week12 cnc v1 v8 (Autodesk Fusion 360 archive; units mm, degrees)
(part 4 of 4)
sketch "Sketch2" plane through (0, 0, 0) normal (-1, 0, 0) x axis (0, -1, 0)
  line L1 (-685.4, 300) -> (-685.4, 288)
  line L2 (-716, 300) -> (-685.4, 300)
  line L3 (-716, 12) -> (-716, 300)
  line L4 (-525.1111, 12) -> (-716, 12)
  line L5 (-525.1111, 0) -> (-525.1111, 12)
  line L6 (-432.8889, 0) -> (-525.1111, 0)
  line L7 (-432.8889, 12) -> (-432.8889, 0)
  line L8 (-243.1111, 12) -> (-432.8889, 12)
  line L9 (-243.1111, 0) -> (-243.1111, 12)
  line L10 (-150.8889, 0) -> (-243.1111, 0)
  line L11 (-150.8889, 12) -> (-150.8889, 0)
  line L12 (0, 12) -> (-150.8889, 12)
  line L13 (0, 300) -> (0, 12)
  line L14 (-656.6, 300) -> (0, 300)
  line L15 (-656.6, 288) -> (-656.6, 300)
  line L16 (-685.4, 288) -> (-656.6, 288)
  line L17 (-614, 12) -> (-626, 12)
  line L18 (-614, 300) -> (-614, 12)
  line L19 (-626, 300) -> (-614, 300)
  line L20 (-626, 12) -> (-626, 300)
  line L21 (-332, 12) -> (-344, 12)
  line L22 (-332, 300) -> (-332, 12)
  line L23 (-344, 300) -> (-332, 300)
  line L24 (-344, 12) -> (-344, 300)
  line L25 (-50, 12) -> (-62, 12)
  line L26 (-50, 300) -> (-50, 12)
  line L27 (-62, 300) -> (-50, 300)
  line L28 (-62, 12) -> (-62, 300)
  line L29 (-896, 12) -> (-908, 12)
  line L30 (-896, 300) -> (-896, 12)
  line L31 (-908, 300) -> (-896, 300)
  line L32 (-908, 12) -> (-908, 300)
  line L33 (-50, 156) -> (-908, 156)
  line L34 (-896, 106) -> (-908, 106)
  line L35 (-614, 106) -> (-626, 106)
  line L36 (-332, 106) -> (-344, 106)
  line L37 (-50, 106) -> (-62, 106)
  line L38 (-50, 206) -> (-62, 206)
  line L39 (-332, 206) -> (-344, 206)
  line L40 (-896, 206) -> (-908, 206)
  line L41 (-614, 206) -> (-626, 206)
  line L42 (-635, 30.4) -> (-707, 30.4)
  line L43 (-635, 48.8) -> (-635, 30.4)
  line L44 (-707, 48.8) -> (-635, 48.8)
  line L45 (-707, 30.4) -> (-707, 48.8)
  line L46 (-707, 300) -> (-635, 300)
  line L47 (-707, 288) -> (-707, 300)
  line L48 (-635, 288) -> (-707, 288)
  line L49 (-635, 300) -> (-635, 288)
  line L50 (-635, 85.6) -> (-635, 67.2)
  line L51 (-707, 67.2) -> (-707, 85.6)
  line L52 (-635, 67.2) -> (-707, 67.2)
  line L53 (-707, 85.6) -> (-635, 85.6)
  line L54 (-635, 122.4) -> (-635, 104)
  line L55 (-707, 159.2) -> (-635, 159.2)
  line L56 (-707, 104) -> (-707, 122.4)
  line L57 (-707, 140.8) -> (-707, 159.2)
  line L58 (-635, 140.8) -> (-707, 140.8)
  line L59 (-635, 159.2) -> (-635, 140.8)
  line L60 (-707, 122.4) -> (-635, 122.4)
  line L61 (-635, 104) -> (-707, 104)
  line L62 (-707, 232.8) -> (-635, 232.8)
  line L63 (-635, 232.8) -> (-635, 214.4)
  line L64 (-635, 177.6) -> (-707, 177.6)
  line L65 (-707, 269.6) -> (-635, 269.6)
  line L66 (-635, 251.2) -> (-707, 251.2)
  line L67 (-707, 214.4) -> (-707, 232.8)
  line L68 (-707, 177.6) -> (-707, 196)
  line L69 (-707, 196) -> (-635, 196)
  line L70 (-635, 214.4) -> (-707, 214.4)
  line L71 (-635, 269.6) -> (-635, 251.2)
  line L72 (-707, 251.2) -> (-707, 269.6)
  line L73 (-635, 196) -> (-635, 177.6)
  line L74 (-671, 12) -> (-671, 30.4)
  line L75 (-671, 67.2) -> (-671, 48.8)
  line L76 (-671, 104) -> (-671, 85.6)
  line L77 (-671, 140.8) -> (-671, 122.4)
  line L78 (-671, 177.6) -> (-671, 159.2)
  line L79 (-671, 214.4) -> (-671, 196)
  line L80 (-671, 251.2) -> (-671, 232.8)
  line L81 (-671, 288) -> (-671, 269.6)
  line L82 (-716, 288) -> (-707, 288)
  line L83 (-626, 288) -> (-635, 288)
  line L84 (-525.1111, 0) -> (-716, 0)
  line L85 (-525.1111, 12) -> (-525.1111, 0)
  line L86 (-716, 12) -> (-525.1111, 12)
  line L87 (-716, 0) -> (-716, 12)
  line L88 (-614, 0) -> (-614, 12)
  line L89 (-116, 228) -> (-116, 84)
  line L90 (-206, 228) -> (-116, 228)
  line L91 (-116, 84) -> (-206, 84)
  line L92 (-488, 228) -> (-398, 228)
  line L93 (-398, 84) -> (-488, 84)
  line L94 (-398, 228) -> (-398, 84)
  line L95 (-680, 228) -> (-680, 84)
  line L96 (-770, 228) -> (-680, 228)
  line L97 (-680, 84) -> (-770, 84)
  arc A1 centre (-206, 156) radius 72 clockwise from (-206, 84) to (-206, 228)
  arc A2 centre (-488, 156) radius 72 clockwise from (-488, 84) to (-488, 228)
  arc A3 centre (-770, 156) radius 72 clockwise from (-770, 84) to (-770, 228)
  point P34 (-908, 156)
  point P35 (-50, 156)
  point P36 (-908, 106)
  point P37 (-896, 106)
  point P38 (-626, 106)
  point P39 (-614, 106)
  point P40 (-344, 106)
  point P41 (-332, 106)
  point P42 (-62, 106)
  point P43 (-50, 106)
  point P46 (-908, 206)
  point P48 (-896, 206)
  point P50 (-626, 206)
  point P47 (-614, 206)
  point P51 (-344, 206)
  point P44 (-332, 206)
  point P49 (-62, 206)
  point P45 (-50, 206)
  point P84 (-671, 30.4)
  point P85 (-671, 12)
  point P86 (-671, 48.8)
  point P87 (-671, 67.2)
  point P88 (-671, 85.6)
  point P89 (-671, 104)
  point P90 (-671, 122.4)
  point P91 (-671, 140.8)
  point P92 (-671, 159.2)
  point P93 (-671, 177.6)
  point P94 (-671, 196)
  point P95 (-671, 214.4)
  point P96 (-671, 232.8)
  point P97 (-671, 251.2)
  point P98 (-671, 269.6)
  point P99 (-671, 288)
  point P58 (-707, 288)
  point P100 (-707, 288)
  point P101 (-716, 288)
  point P59 (-635, 288)
  point P102 (-635, 288)
  point P103 (-626, 288)
  point P19 (-614, 12)
  point P108 (-614, 12)
  point P109 (-614, 0)
  point P115 (-278, 156)
  point P117 (-560, 156)
  point P126 (-842, 156)
  point P110 (-116, 84)
  point P111 (-116, 228)
  point P118 (-398, 228)
  point P120 (-398, 84)
  point P123 (-680, 228)
  point P127 (-680, 84)
  midpoint L32 P34
  midpoint L26 P35
  coincident L32 P36
  coincident L30 P37
  perpendicular L30 L34
  coincident L20 P38
  coincident L18 P39
  perpendicular L18 L35
  coincident L24 P40
  coincident L22 P41
  perpendicular L22 L36
  coincident L28 P42
  coincident L26 P43
  perpendicular L26 L37
  collinear L34 L35
  collinear L35 L36
  collinear L36 L37
  symmetric L33 P36 P46
  symmetric L33 P37 P48
  symmetric L33 P38 P50
  symmetric L33 P39 P47
  symmetric L33 P40 P51
  symmetric L33 P41 P44
  symmetric L33 P42 P49
  symmetric L33 P43 P45
  horizontal L42
  vertical L43
  horizontal L44
  vertical L45
  collinear L45 L47
  collinear L43 L49
  horizontal L52
  vertical L50
  horizontal L53
  vertical L51
  horizontal L61
  vertical L54
  horizontal L60
  vertical L56
  horizontal L58
  vertical L59
  horizontal L55
  vertical L57
  horizontal L64
  vertical L73
  horizontal L69
  vertical L68
  horizontal L70
  vertical L63
  horizontal L62
  vertical L67
  horizontal L66
  vertical L71
  horizontal L65
  vertical L72
  equal L45 L51
  equal L51 L56
  equal L56 L57
  equal L57 L68
  equal L67 L68
  equal L67 L72
  collinear L57 L72
  collinear L51 L57
  collinear L51 L67
  collinear L45 L67
  collinear L45 L68
  collinear L56 L68
  collinear L43 L54
  collinear L54 L59
  collinear L59 L63
  collinear L63 L73
  collinear L50 L73
  collinear L50 L71
  midpoint L42 P84
  coincident L4 P85
  perpendicular L4 L74
  midpoint L44 P86
  midpoint L52 P87
  midpoint L53 P88
  midpoint L61 P89
  midpoint L60 P90
  midpoint L58 P91
  midpoint L55 P92
  midpoint L64 P93
  midpoint L69 P94
  midpoint L70 P95
  midpoint L62 P96
  midpoint L66 P97
  midpoint L65 P98
  midpoint L48 P99
  equal L45 L74
  equal L79 L80
  equal L77 L80
  equal L75 L77
  equal L74 L75
  equal L74 L76
  equal L76 L78
  equal L78 L81
  coincident P58 P100
  coincident L3 P101
  perpendicular L3 L82
  coincident P59 P102
  coincident L20 P103
  perpendicular L20 L83
  coincident P19 P108
  coincident L84 P109
  perpendicular L84 L88
  vertical L89
  perpendicular L89 L90
  tangent L90 A1
  symmetric L33 L90 L91
  tangent A1 L91
  midpoint A1 P115
  vertical L94
  perpendicular L92 L94
  tangent A2 L92
  tangent A2 L93
  midpoint P117 A2
  perpendicular L93 L94
  vertical L95
  perpendicular L95 L96
  tangent L96 A3
  tangent L97 A3
  midpoint P126 A3
  perpendicular L95 L97
  coincident L33 P117
  coincident L33 P126
  equal L92 L96
  dimension "d55" distance L34 L40 = 100 (= "width / 3")
  dimension "d58" distance L22 L28 = 270
  dimension "d59" distance L28 L89 = 54 (= "d58 / 5")
  dimension "d60" distance L12 L14 = 288
  dimension "d61" distance L22 P115 = 54 (= "d58 / 5")
  dimension "d62" distance P110 P111 = 144 (= "d60 * 0.5")
  dimension "d63" distance P118 P120 = 144 (= "d60 * 0.5")
  dimension "d64" distance P123 P127 = 144 (= "d60 * 0.5")
  dimension "d66" distance L24 L94 = 54 (= "d59")
  dimension "d67" distance L30 P126 = 54 (= "d65")
extrude "Extrude10" cut sketch "Sketch2" profile of L42 L43 L44 L45 L50 L51 L52 L53 L54 L55 L56 L57 L58 L59 L60 L61 L62 L63 L64 L65 L66 L67 L68 L69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 to an object
extrude "Extrude5" cut sketch "Sketch2" profile of L89 L90 A1 L91 A2 L92 L93 L94 to an object
extrude "Extrude6" sketch "Sketch2" profile of L3 L51 L53 L55 L56 L57 L58 L60 L61 L64 L67 L68 L69 L70 L89 L90 A1 L91 A2 L92 L93 L94 L95 L96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 to an object
sketch "Sketch3" plane through (541.3333, 0, 0) normal (1, 0, 0) x axis (0, 1, 0)
  line L1 (626, 12) -> (332, 12)
  line L2 (626, 300) -> (626, 12)
  line L3 (332, 300) -> (626, 300)
  line L4 (332, 12) -> (332, 300)
  line L5 (626, 12) -> (614, 12)
  line L6 (626, 300) -> (626, 12)
  line L7 (614, 300) -> (626, 300)
  line L8 (614, 12) -> (614, 300)
  line L9 (344, 12) -> (332, 12)
  line L10 (344, 300) -> (344, 12)
  line L11 (332, 300) -> (344, 300)
  line L12 (332, 12) -> (332, 300)
  line L13 (62, 12) -> (50, 12)
  line L14 (62, 300) -> (62, 12)
  line L15 (50, 300) -> (62, 300)
  line L16 (50, 12) -> (50, 300)
  line L17 (116, 84) -> (206, 84)
  line L18 (206, 228) -> (116, 228)
  line L19 (116, 228) -> (116, 84)
  line L20 (62, 228) -> (165.5, 228)
  line L21 (62, 84) -> (165.5, 84)
  line L22 (344, 228) -> (447.5, 228)
  line L23 (344, 84) -> (447.5, 84)
  line L24 (626, 228) -> (729.5, 228)
  line L25 (626, 84) -> (729.5, 84)
  line L26 (908, 12) -> (896, 12)
  line L27 (908, 300) -> (908, 12)
  line L28 (896, 300) -> (908, 300)
  line L29 (896, 12) -> (896, 300)
  line L30 (50, 156) -> (908, 156)
  line L31 (896, 106) -> (908, 106)
  line L32 (614, 106) -> (626, 106)
  line L33 (332, 106) -> (344, 106)
  line L34 (50, 106) -> (62, 106)
  line L35 (896, 206) -> (908, 206)
  line L36 (614, 206) -> (626, 206)
  line L37 (332, 206) -> (344, 206)
  line L38 (50, 206) -> (62, 206)
  line L39 (626, 300) -> (626, 228)
  line L40 (614, 264) -> (626, 264)
  line L41 (614, 252) -> (626, 252)
  line L42 (614, 276) -> (626, 276)
  line L43 (614, 60) -> (626, 60)
  line L44 (614, 36) -> (626, 36)
  line L45 (479, 300) -> (479, 12)
  line L46 (197, 300) -> (197, 12)
  line L47 (344, 36) -> (332, 36)
  line L48 (344, 60) -> (332, 60)
  line L49 (344, 252) -> (332, 252)
  line L50 (344, 276) -> (332, 276)
  line L51 (50, 36) -> (62, 36)
  line L52 (50, 60) -> (62, 60)
  line L53 (50, 252) -> (62, 252)
  line L54 (50, 276) -> (62, 276)
  arc A1 centre (206, 156) radius 72 clockwise from (206, 228) to (206, 84)
  arc A2 centre (165.5, 156) radius 72 clockwise from (165.5, 228) to (165.5, 84)
  arc A3 centre (447.5, 156) radius 72 clockwise from (447.5, 228) to (447.5, 84)
  arc A4 centre (729.5, 156) radius 72 clockwise from (729.5, 228) to (729.5, 84)
  point P23 (165.5, 228)
  point P24 (62, 228)
  point P25 (165.5, 84)
  point P26 (62, 84)
  point P28 (237.5, 156)
  point P33 (344, 228)
  point P30 (344, 84)
  point P38 (626, 228)
  point P35 (626, 84)
  point P43 (908, 156)
  point P44 (50, 156)
  point P45 (908, 106)
  point P46 (896, 106)
  point P47 (626, 106)
  point P48 (614, 106)
  point P49 (344, 106)
  point P50 (332, 106)
  point P51 (62, 106)
  point P52 (50, 106)
  point P53 (908, 206)
  point P54 (896, 206)
  point P55 (626, 206)
  point P56 (614, 206)
  point P57 (344, 206)
  point P58 (332, 206)
  point P59 (62, 206)
  point P60 (50, 206)
  point P4 (626, 300)
  point P61 (626, 300)
  point P62 (626, 264)
  point P63 (614, 264)
  point P64 (626, 252)
  point P65 (614, 252)
  point P66 (626, 276)
  point P67 (614, 276)
  point P68 (626, 60)
  point P69 (614, 60)
  point P70 (626, 36)
  point P71 (614, 36)
  point P74 (197, 12)
  point P72 (479, 12)
  point P80 (332, 252)
  point P81 (344, 252)
  point P82 (332, 276)
  point P83 (344, 276)
  point P78 (332, 60)
  point P79 (344, 60)
  point P76 (332, 36)
  point P77 (344, 36)
  point P84 (62, 36)
  point P85 (50, 36)
  point P86 (62, 60)
  point P87 (50, 60)
  point P88 (62, 252)
  point P89 (50, 252)
  point P90 (62, 276)
  point P91 (50, 276)
  point P92 (908, 300)
  point P93 (896, 300)
  point P94 (908, 300)
  point P95 (896, 300)
  point P96 (908, 300)
  point P97 (896, 300)
  coincident L18 P23
  coincident L14 P24
  perpendicular L14 L20
  coincident L17 P25
  coincident L14 P26
  perpendicular L14 L21
  tangent L20 A2
  tangent L21 A2
  midpoint A2 P28
  tangent L22 A3
  tangent A3 L23
  tangent L24 A4
  tangent A4 L25
  coincident L10 P33
  coincident L10 P30
  collinear L20 L22
  collinear L21 L23
  equal L21 L23
  coincident L6 P38
  coincident L6 P35
  collinear L22 L24
  collinear L23 L25
  equal L23 L25
  midpoint L27 P43
  midpoint L16 P44
  coincident L27 P45
  coincident L29 P46
  perpendicular L29 L31
  coincident L6 P47
  coincident L8 P48
  perpendicular L8 L32
  coincident L10 P49
  coincident L12 P50
  perpendicular L12 L33
  coincident L14 P51
  coincident L16 P52
  perpendicular L16 L34
  collinear L33 L34
  collinear L32 L33
  collinear L31 L32
  symmetric L30 P45 P53
  symmetric L30 P46 P54
  symmetric L30 P47 P55
  symmetric L30 P48 P56
  symmetric L30 P49 P57
  symmetric L30 P50 P58
  symmetric L30 P51 P59
  symmetric L30 P52 P60
  coincident P4 P61
  midpoint L39 P62
  coincident L8 P63
  perpendicular L8 L40
  coincident L39 P64
  coincident L8 P65
  perpendicular L8 L41
  coincident L6 P66
  coincident L8 P67
  perpendicular L8 L42
  symmetric L40 L41 L42
  symmetric L30 P64 P68
  symmetric L30 P65 P69
  symmetric L30 P66 P70
  symmetric L30 P67 P71
  perpendicular L30 L45
  perpendicular L30 L46
  symmetric L8 L10 L45
  equal L45 L46
  equal L10 L45
  coincident L1 P74
  coincident L1 P72
  symmetric P64 L45 P80
  symmetric P65 L45 P81
  symmetric P66 L45 P82
  symmetric P67 L45 P83
  symmetric P68 L45 P78
  symmetric P69 L45 P79
  symmetric P70 L45 P76
  symmetric P71 L45 P77
  symmetric L46 P76 P84
  symmetric L46 P77 P85
  symmetric L46 P78 P86
  symmetric L46 P79 P87
  symmetric L46 P80 P88
  symmetric L46 P81 P89
  symmetric L46 P82 P90
  symmetric L46 P83 P91
  dimension "d73" distance L12 L14 = 270
  dimension "d74" distance L12 P28 = 94.5 (= "d73 * 0.35")
  dimension "d75" distance L31 L35 = 100 (= "width / 3")
  dimension "d76" distance L3 L24 = 72
  dimension "d77" distance L41 L42 = 24 (= "d76 / 3")
  dimension "d87" distance P92 P93 = 12
  dimension "d88" distance P94 P95 = 12
  dimension "d89" distance P96 P97 = 12
extrude "Extrude7" cut sketch "Sketch3" profile of L1 L2 L3 L4 L5 L6 L7 L8 L9 L10 L11 L12 L22 A3 L23 L32 L33 L36 L37 L41 L42 L43 L44 L47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 to an object
extrude "Extrude8" sketch "Sketch3" profile of L1 L2 L3 L4 L5 L6 L7 L8 L9 L10 L11 L12 L13 L14 L15 L16 L20 L21 A2 L24 A4 L25 L26 L27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 to an object
extrude "Extrude9" cut sketch "Sketch2" profile of L18 L20 L22 L24 L26 L28 L30 L32 L34 L35 L36 L37 L38 L39 L40 L41 to an object
combine "Combine13"
combine "Combine14"
combine "Combine15" Linear Dimension-10 54 (= "d61") named "d65"
combine "Combine16"
sketch "Sketch5" plane through (0, 626, 0) normal (0, 1, 0) x axis (-1, 0, 0)
  line L1 (-12, 300) -> (-12, 206)
  line L2 (-104.2222, 300) -> (-12, 300)
  line L3 (-104.2222, 288) -> (-104.2222, 300)
  line L4 (-196.4444, 288) -> (-104.2222, 288)
  line L5 (-196.4444, 300) -> (-196.4444, 288)
  line L6 (-818, 300) -> (-196.4444, 300)
  line L7 (-818, 206) -> (-818, 300)
  line L8 (-830, 206) -> (-818, 206)
  line L9 (-830, 106) -> (-830, 206)
  line L10 (-818, 106) -> (-830, 106)
  line L11 (-818, 12) -> (-818, 106)
  line L12 (-725.7778, 12) -> (-818, 12)
  line L13 (-725.7778, 0) -> (-725.7778, 12)
  line L14 (-633.5556, 0) -> (-725.7778, 0)
  line L15 (-633.5556, 12) -> (-633.5556, 0)
  line L16 (-196.4444, 12) -> (-633.5556, 12)
  line L17 (-196.4444, 0) -> (-196.4444, 12)
  line L18 (-104.2222, 0) -> (-196.4444, 0)
  line L19 (-104.2222, 12) -> (-104.2222, 0)
  line L20 (-12, 12) -> (-104.2222, 12)
  line L21 (-12, 106) -> (-12, 12)
  line L22 (0, 106) -> (-12, 106)
  line L23 (0, 206) -> (0, 106)
  line L24 (-12, 206) -> (0, 206)
  line L25 (-300.6667, 36) -> (-288.6667, 36)
  line L26 (-300.6667, 60) -> (-300.6667, 36)
  line L27 (-288.6667, 60) -> (-300.6667, 60)
  line L28 (-288.6667, 36) -> (-288.6667, 60)
  line L29 (-300.6667, 276) -> (-300.6667, 252)
  line L30 (-288.6667, 276) -> (-300.6667, 276)
  line L31 (-288.6667, 252) -> (-288.6667, 276)
  line L32 (-300.6667, 252) -> (-288.6667, 252)
  line L33 (-541.3333, 106) -> (-529.3333, 106)
  line L34 (-541.3333, 206) -> (-541.3333, 106)
  line L35 (-529.3333, 206) -> (-541.3333, 206)
  line L36 (-529.3333, 106) -> (-529.3333, 206)
  line L37 (-750, 50) -> (-650, 50)
  line L38 (-750, 140) -> (-750, 50)
  line L39 (-650, 140) -> (-750, 140)
  line L40 (-650, 50) -> (-650, 140)
  point P38 (-650, 50)
  point P39 (-750, 50)
  point P41 (-650, 140)
  horizontal L37
  vertical L38
  horizontal L39
  vertical L40
  dimension "d123" distance P38 P39 = 100
  dimension "d124" distance P38 P41 = 90
extrude "Extrude11" cut sketch "Sketch5" profile of L37 L38 L39 L40 no distance stored
sketch "Sketch6" plane through (0, 344, 0) normal (0, 1, 0) x axis (-1, 0, 0)
  line L1 (-300.6667, 106) -> (-288.6667, 106)
  line L2 (-300.6667, 206) -> (-300.6667, 106)
  line L3 (-288.6667, 206) -> (-300.6667, 206)
  line L4 (-288.6667, 106) -> (-288.6667, 206)
  line L5 (-529.3333, 276) -> (-541.3333, 276)
  line L6 (-529.3333, 252) -> (-529.3333, 276)
  line L7 (-541.3333, 252) -> (-529.3333, 252)
  line L8 (-541.3333, 276) -> (-541.3333, 252)
  line L9 (-541.3333, 36) -> (-529.3333, 36)
  line L10 (-541.3333, 60) -> (-541.3333, 36)
  line L11 (-529.3333, 60) -> (-541.3333, 60)
  line L12 (-529.3333, 36) -> (-529.3333, 60)
  line L13 (-818, 206) -> (-818, 300)
  line L14 (-830, 206) -> (-818, 206)
  line L15 (-830, 106) -> (-830, 206)
  line L16 (-818, 106) -> (-830, 106)
  line L17 (-818, 12) -> (-818, 106)
  line L18 (-725.7778, 12) -> (-818, 12)
  line L19 (-725.7778, 0) -> (-725.7778, 12)
  line L20 (-633.5556, 0) -> (-725.7778, 0)
  line L21 (-633.5556, 12) -> (-633.5556, 0)
  line L22 (-196.4444, 12) -> (-633.5556, 12)
  line L23 (-196.4444, 0) -> (-196.4444, 12)
  line L24 (-104.2222, 0) -> (-196.4444, 0)
  line L25 (-104.2222, 12) -> (-104.2222, 0)
  line L26 (-12, 12) -> (-104.2222, 12)
  line L27 (-12, 106) -> (-12, 12)
  line L28 (0, 106) -> (-12, 106)
  line L29 (0, 206) -> (0, 106)
  line L30 (-12, 206) -> (0, 206)
  line L31 (-12, 300) -> (-12, 206)
  line L32 (-818, 300) -> (-12, 300)
  line L33 (-175, 50) -> (-75, 50)
  line L34 (-175, 140) -> (-175, 50)
  line L35 (-75, 140) -> (-175, 140)
  line L36 (-75, 50) -> (-75, 140)
  point P34 (-75, 50)
  point P35 (-175, 50)
  point P37 (-75, 140)
  horizontal L33
  vertical L34
  horizontal L35
  vertical L36
  dimension "d129" distance P34 P35 = 100
  dimension "d130" distance P34 P37 = 90
extrude "Extrude12" cut sketch "Sketch6" profile of L33 L34 L35 L36 no distance stored
sketch "Sketch7" plane through (0, 344, 0) normal (0, 1, 0) x axis (-1, 0, 0)
  line L1 (1386, 0) -> (0, 0)
  line L2 (1386, 3576.0999) -> (1386, 0)
  line L3 (0, 3576.0999) -> (1386, 3576.0999)
  line L4 (0, 0) -> (0, 3576.0999)
  horizontal L1
  vertical L2
  horizontal L3
  vertical L4
sketch "Sketch8" plane through (0, 0, 12) normal (0, 0, 1) x axis (-1, 0, 0)
  line L1 (-251.7778, -635) -> (-270.2222, -635)
  line L2 (-251.7778, -707) -> (-251.7778, -635)
  line L3 (-270.2222, -707) -> (-251.7778, -707)
  line L4 (-270.2222, -635) -> (-270.2222, -707)
  line L5 (-178, -635) -> (-196.4444, -635)
  line L6 (-178, -707) -> (-178, -635)
  line L7 (-196.4444, -707) -> (-178, -707)
  line L8 (-196.4444, -635) -> (-196.4444, -707)
  line L9 (-214.8889, -635) -> (-233.3333, -635)
  line L10 (-214.8889, -707) -> (-214.8889, -635)
  line L11 (-233.3333, -707) -> (-214.8889, -707)
  line L12 (-233.3333, -635) -> (-233.3333, -707)
  line L13 (-141.1111, -635) -> (-159.5556, -635)
  line L14 (-141.1111, -707) -> (-141.1111, -635)
  line L15 (-159.5556, -707) -> (-141.1111, -707)
  line L16 (-159.5556, -635) -> (-159.5556, -707)
  line L17 (-104.2222, -635) -> (-122.6667, -635)
  line L18 (-104.2222, -707) -> (-104.2222, -635)
  line L19 (-122.6667, -707) -> (-104.2222, -707)
  line L20 (-122.6667, -635) -> (-122.6667, -707)
  line L21 (-538.5833, -1038.7015) -> (-517.8333, -1002.7614)
  line L22 (-580.0833, -1038.7015) -> (-538.5833, -1038.7015)
  line L23 (-600.8333, -1002.7614) -> (-580.0833, -1038.7015)
  line L24 (-580.0833, -966.8214) -> (-600.8333, -1002.7614)
  line L25 (-538.5833, -966.8214) -> (-580.0833, -966.8214)
  line L26 (-517.8333, -1002.7614) -> (-538.5833, -966.8214)
  line L27 (-104.2222, -62) -> (-104.2222, -50)
  line L28 (-196.4444, -62) -> (-104.2222, -62)
  line L29 (-196.4444, -50) -> (-196.4444, -62)
  line L30 (-104.2222, -50) -> (-196.4444, -50)
  line L31 (-30.4444, -635) -> (-48.8889, -635)
  line L32 (-30.4444, -707) -> (-30.4444, -635)
  line L33 (-48.8889, -707) -> (-30.4444, -707)
  line L34 (-48.8889, -635) -> (-48.8889, -707)
  line L35 (-67.3333, -635) -> (-85.7778, -635)
  line L36 (-67.3333, -707) -> (-67.3333, -635)
  line L37 (-85.7778, -707) -> (-67.3333, -707)
  line L38 (-85.7778, -635) -> (-85.7778, -707)
  line L39 (-104.2222, -626) -> (-104.2222, -614)
  line L40 (-196.4444, -626) -> (-104.2222, -626)
  line L41 (-196.4444, -614) -> (-196.4444, -626)
  line L42 (-104.2222, -614) -> (-196.4444, -614)
  line L43 (-104.2222, -332) -> (-196.4444, -332)
  line L44 (-104.2222, -344) -> (-104.2222, -332)
  line L45 (-196.4444, -344) -> (-104.2222, -344)
  line L46 (-196.4444, -332) -> (-196.4444, -344)
  line L47 (-633.5556, -626) -> (-633.5556, -614)
  line L48 (-725.7778, -626) -> (-633.5556, -626)
  line L49 (-725.7778, -614) -> (-725.7778, -626)
  line L50 (-633.5556, -614) -> (-725.7778, -614)
  line L51 (-725.7778, -332) -> (-725.7778, -344)
  line L52 (-633.5556, -332) -> (-725.7778, -332)
  line L53 (-633.5556, -344) -> (-633.5556, -332)
  line L54 (-725.7778, -344) -> (-633.5556, -344)
  line L55 (-513.2222, -908) -> (-513.2222, -896)
  line L56 (-605.4444, -908) -> (-513.2222, -908)
  line L57 (-605.4444, -896) -> (-605.4444, -908)
  line L58 (-513.2222, -896) -> (-605.4444, -896)
  line L59 (-633.5556, -62) -> (-633.5556, -50)
  line L60 (-725.7778, -62) -> (-633.5556, -62)
  line L61 (-725.7778, -50) -> (-725.7778, -62)
  line L62 (-633.5556, -50) -> (-725.7778, -50)
  line L63 (-830, -807.1111) -> (-818, -807.1111)
  line L64 (-830, -908) -> (-830, -807.1111)
  line L65 (-559.3333, -1097.5228) -> (-830, -908)
  line L66 (-288.6667, -908) -> (-559.3333, -1097.5228)
  line L67 (-288.6667, -716) -> (-288.6667, -908)
  line L68 (0, -716) -> (-288.6667, -716)
  line L69 (0, -525.1111) -> (0, -716)
  line L70 (-12, -525.1111) -> (0, -525.1111)
  line L71 (-12, -432.8889) -> (-12, -525.1111)
  line L72 (0, -432.8889) -> (-12, -432.8889)
  line L73 (0, -243.1111) -> (0, -432.8889)
  line L74 (-12, -243.1111) -> (0, -243.1111)
  line L75 (-12, -150.8889) -> (-12, -243.1111)
  line L76 (0, -150.8889) -> (-12, -150.8889)
  line L77 (0, 0) -> (0, -150.8889)
  line L78 (-830, 0) -> (0, 0)
  line L79 (-830, -150.8889) -> (-830, 0)
  line L80 (-818, -150.8889) -> (-830, -150.8889)
  line L81 (-818, -243.1111) -> (-818, -150.8889)
  line L82 (-830, -243.1111) -> (-818, -243.1111)
  line L83 (-830, -714.8889) -> (-830, -243.1111)
  line L84 (-818, -714.8889) -> (-830, -714.8889)
  line L85 (-818, -807.1111) -> (-818, -714.8889)
  line L86 (-830, -50) -> (0, -50)
  line L87 (-830, 0) -> (-830, -50)
  line L88 (0, 0) -> (-830, 0)
  line L89 (0, -50) -> (0, 0)
  line L90 (0, 0) -> (0, -150.8889)
  point P80 (-830, 0)
  point P89 (-830, 0)
  point P87 (0, -50)
  horizontal L86
  vertical L87
  horizontal L88
  vertical L89
  coincident P80 P89
  coincident L77 P87
extrude "Extrude13" new body sketch "Sketch8" profile of L30 L62 L77 L78 L79 L86 L87 L88 L89 L90 blind 12 (= "ply_Thickness") from offset 300 (= "width") bodies "kerf"
extrude "Extrude14" cut of existing geometry no distance stored
extrude "Extrude15" cut of existing geometry no distance stored
move "Move1"
sketch "Sketch9" plane through (818, 0, 0) normal (1, 0, 0) x axis (0, 1, 0)
  line L1 (50, 288) -> (0, 288)
  line L2 (50, 300) -> (50, 288)
  line L3 (0, 300) -> (50, 300)
  line L4 (0, 288) -> (0, 300)
  line L5 (25, 300) -> (25, 288)
  line L6 (32.5, 300) -> (17.5, 300)
  line L7 (32.5, 288) -> (32.5, 300)
  line L8 (17.5, 288) -> (32.5, 288)
  line L9 (17.5, 300) -> (17.5, 288)
  line L10 (32.5, 288) -> (17.5, 300)
  line L11 (17.5, 288) -> (32.5, 300)
  line L12 (0, 288) -> (50, 288)
  line L13 (0, 300) -> (0, 288)
  line L14 (50, 300) -> (0, 300)
  line L15 (50, 288) -> (50, 300)
  line L16 (17.5, 300) -> (32.5, 300)
  line L17 (17.5, 288) -> (17.5, 300)
  line L18 (32.5, 288) -> (17.5, 288)
  line L19 (32.5, 300) -> (32.5, 288)
  line L20 (17.5, 288) -> (32.5, 300)
  line L21 (32.5, 288) -> (17.5, 300)
  point P6 (25, 288)
  point P7 (25, 300)
  point P12 (25, 294)
  point P21 (25, 294)
  point P10 (32.5, 288)
  point P11 (17.5, 288)
  point P9 (32.5, 300)
  point P19 (17.5, 288)
  point P20 (32.5, 288)
  point P18 (17.5, 300)
  midpoint L1 P6
  midpoint L3 P7
  horizontal L6
  perpendicular L6 L7
  parallel L6 L8
  parallel L7 L9
  coincident L10 P12
  coincident L11 P12
  midpoint L5 P12
  horizontal L16
  perpendicular L16 L17
  parallel L16 L18
  parallel L17 L19
  coincident L20 P21
  coincident L21 P21
  coincident P12 P21
  dimension "d18" = 270 (= "d17")
  dimension "d140" distance P10 P11 = 15
  dimension "d141" distance P9 P10 = 12 (= "ply_Thickness")
  dimension "d142" distance P19 P20 = 15
  dimension "d143" distance P18 P19 = 12 (= "ply_Thickness")
extrude "Extrude16" new body sketch "Sketch9" profile of L1 L3 L5 L6 L7 L8 L9 L12 L14 L16 L17 L18 L19 along normal blind 12 (= "ply_Thickness")
copy_paste_bodies "CopyPasteBodies1"
move "Move2"
extrude "Extrude17" add of existing geometry blind 3
extrude "Extrude18" add of existing geometry blind 3
extrude "Extrude19" add of existing geometry blind 3
extrude "Extrude20" add of existing geometry blind 3
combine "Combine17"
combine "Combine18"
component_from_bodies "Body->Comp12"
component_from_bodies "Body->Comp13"
component_from_bodies "Body->Comp14"
component_from_bodies "Body->Comp15"
component_from_bodies "Body->Comp16"
component_from_bodies "Body->Comp17"
component_from_bodies "Body->Comp18"
component_from_bodies "Body->Comp19"
component_from_bodies "Body->Comp20"
component_from_bodies "Body->Comp21"
component_from_bodies "Body->Comp22"
component_from_bodies "Body->Comp23"
step "Arrange" AngleFromX 0 Priority 500 AngleFromX 0 Priority 500 AngleFromX 0 Priority 500 AngleFromX 0 Priority 500 AngleFromX 0 Priority 500 AngleFromX 0 Priority 500 AngleFromX 0 Priority 500 AngleFromX 0 Priority 500 AngleFromX 0 Priority 500 AngleFromX 0 Priority 500 AngleFromX 0 Priority 500 AngleFromX 0 Priority 500 originOffsetX 0 originOffsetY 1400 envelopeLength 1219.2 (= "4 ft") envelopeWidth 2438.4 (= "8 ft") envelopeSpacing 0 grainDirection 0 objectSpacing 30 frameWidth 20 placementClearance 30
chamfer "Chamfer1" distance 3
base_feature "Base Feature2" bodies "Dogbones"
combine "Combine1"
base_feature "Base Feature3" bodies "Dogbones (1)"
combine "Combine1"
base_feature "Base Feature4" bodies "Dogbones1", "Dogbones2"
combine "Combine1"
combine "Combine1"
base_feature "Base Feature5" bodies "Dogbones (2)"
combine "Combine1"
base_feature "Base Feature6" bodies "Dogbones (3)"
combine "Combine1"
base_feature "Base Feature7" bodies "Dogbones (4)"
combine "Combine1"
base_feature "Base Feature8" bodies "Dogbones (5)"
combine "Combine1"
base_feature "Base Feature9" bodies "Dogbones (6)"
combine "Combine2"
base_feature "Base Feature10" bodies "Dogbones (7)"
combine "Combine1"
chamfer "Chamfer1" distance 3
chamfer "Chamfer1" distance 3
chamfer "Chamfer1" distance 3
chamfer "Chamfer1" distance 3
chamfer "Chamfer1" distance 3
chamfer "Chamfer2" distance 3
chamfer "Chamfer1" distance 3
chamfer "Chamfer2" distance 3
chamfer "Chamfer2" distance 3
chamfer "Chamfer3" distance 3
chamfer "Chamfer1" distance 3
chamfer "Chamfer2" distance 3
chamfer "Chamfer2" distance 3
sketch "Sketch13" plane through (0, 42, 0) normal (0, 1, 0) x axis (-1, 0, 0)
  line L1 (-2459.8014, 745.7778) -> (-2463.2443, 745.7778)
  line L2 (-2455.5228, 657.8341) -> (-2455.5228, 741.4992)
  line L3 (-2463.2443, 653.5556) -> (-2459.8014, 653.5556)
  line L4 (-2467.5228, 741.4992) -> (-2467.5228, 657.8341)
  line L5 (-2459.8014, 216.4444) -> (-2463.2443, 216.4444)
  line L6 (-2455.5228, 128.5008) -> (-2455.5228, 212.1659)
  line L7 (-2463.2443, 124.2222) -> (-2459.8014, 124.2222)
  line L8 (-2467.5228, 212.1659) -> (-2467.5228, 128.5008)
  line L9 (-2366.6339, 850) -> (-2366.6339, 842.2786)
  line L10 (-2517.5228, 850) -> (-2366.6339, 850)
  line L11 (-2517.5228, 20) -> (-2517.5228, 850)
  line L12 (-2366.6339, 20) -> (-2517.5228, 20)
  line L13 (-2366.6339, 27.7214) -> (-2366.6339, 20)
  line L14 (-2278.6903, 32) -> (-2362.3554, 32)
  line L15 (-2274.4117, 20) -> (-2274.4117, 27.7214)
  line L16 (-1802.6339, 20) -> (-2274.4117, 20)
  line L17 (-1802.6339, 27.7214) -> (-1802.6339, 20)
  line L18 (-1714.6903, 32) -> (-1798.3554, 32)
  line L19 (-1710.4117, 20) -> (-1710.4117, 27.7214)
  line L20 (-1609.5228, 20) -> (-1710.4117, 20)
  line L21 (-1420, 290.6667) -> (-1609.5228, 20)
  line L22 (-1609.5228, 561.3333) -> (-1420, 290.6667)
  line L23 (-1801.5228, 561.3333) -> (-1609.5228, 561.3333)
  line L24 (-1801.5228, 850) -> (-1801.5228, 561.3333)
  line L25 (-1992.4117, 850) -> (-1801.5228, 850)
  line L26 (-1992.4117, 842.2786) -> (-1992.4117, 850)
  line L27 (-2080.3554, 838) -> (-1996.6903, 838)
  line L28 (-2084.6339, 850) -> (-2084.6339, 842.2786)
  line L29 (-2274.4117, 850) -> (-2084.6339, 850)
  line L30 (-2274.4117, 842.2786) -> (-2274.4117, 850)
  line L31 (-2362.3554, 838) -> (-2278.6903, 838)
  line L32 (-2181.2443, 653.5556) -> (-2177.8014, 653.5556)
  line L33 (-2185.5228, 741.4992) -> (-2185.5228, 657.8341)
  line L34 (-2177.8014, 745.7778) -> (-2181.2443, 745.7778)
  line L35 (-2173.5228, 657.8341) -> (-2173.5228, 741.4992)
  line L36 (-2181.2443, 124.2222) -> (-2177.8014, 124.2222)
  line L37 (-2185.5228, 212.1659) -> (-2185.5228, 128.5008)
  line L38 (-2177.8014, 216.4444) -> (-2181.2443, 216.4444)
  line L39 (-2173.5228, 128.5008) -> (-2173.5228, 212.1659)
  line L40 (-1903.5228, 741.4992) -> (-1903.5228, 657.8341)
  line L41 (-1895.8014, 745.7778) -> (-1899.2443, 745.7778)
  line L42 (-1891.5228, 657.8341) -> (-1891.5228, 741.4992)
  line L43 (-1899.2443, 653.5556) -> (-1895.8014, 653.5556)
  line L44 (-1895.8014, 216.4444) -> (-1899.2443, 216.4444)
  line L45 (-1891.5228, 128.5008) -> (-1891.5228, 212.1659)
  line L46 (-1899.2443, 124.2222) -> (-1895.8014, 124.2222)
  line L47 (-1903.5228, 212.1659) -> (-1903.5228, 128.5008)
  line L48 (-1613.8014, 336.7778) -> (-1617.2443, 336.7778)
  line L49 (-1609.5228, 248.8341) -> (-1609.5228, 332.4992)
  line L50 (-1617.2443, 244.5556) -> (-1613.8014, 244.5556)
  line L51 (-1621.5228, 332.4992) -> (-1621.5228, 248.8341)
  line L52 (-1882.5228, 598.2222) -> (-1882.5228, 579.7778)
  line L53 (-1810.5228, 598.2222) -> (-1882.5228, 598.2222)
  line L54 (-1810.5228, 579.7778) -> (-1810.5228, 598.2222)
  line L55 (-1882.5228, 579.7778) -> (-1810.5228, 579.7778)
  line L56 (-1882.5228, 672) -> (-1882.5228, 653.5556)
  line L57 (-1810.5228, 672) -> (-1882.5228, 672)
  line L58 (-1810.5228, 653.5556) -> (-1810.5228, 672)
  line L59 (-1882.5228, 653.5556) -> (-1810.5228, 653.5556)
  line L60 (-1882.5228, 635.1111) -> (-1882.5228, 616.6667)
  line L61 (-1810.5228, 635.1111) -> (-1882.5228, 635.1111)
  line L62 (-1810.5228, 616.6667) -> (-1810.5228, 635.1111)
  line L63 (-1882.5228, 616.6667) -> (-1810.5228, 616.6667)
  line L64 (-1882.5228, 708.8889) -> (-1882.5228, 690.4444)
  line L65 (-1810.5228, 708.8889) -> (-1882.5228, 708.8889)
  line L66 (-1810.5228, 690.4444) -> (-1810.5228, 708.8889)
  line L67 (-1882.5228, 690.4444) -> (-1810.5228, 690.4444)
  line L68 (-1882.5228, 745.7778) -> (-1882.5228, 727.3333)
  line L69 (-1810.5228, 745.7778) -> (-1882.5228, 745.7778)
  line L70 (-1810.5228, 727.3333) -> (-1810.5228, 745.7778)
  line L71 (-1882.5228, 727.3333) -> (-1810.5228, 727.3333)
  line L72 (-1478.8214, 311.4167) -> (-1514.7614, 332.1667)
  line L73 (-1478.8214, 269.9167) -> (-1478.8214, 311.4167)
  line L74 (-1514.7614, 249.1667) -> (-1478.8214, 269.9167)
  line L75 (-1550.7015, 269.9167) -> (-1514.7614, 249.1667)
  line L76 (-1550.7015, 311.4167) -> (-1550.7015, 269.9167)
  line L77 (-1514.7614, 332.1667) -> (-1550.7015, 311.4167)
  line L78 (-1882.5228, 819.5556) -> (-1882.5228, 801.1111)
  line L79 (-1810.5228, 819.5556) -> (-1882.5228, 819.5556)
  line L80 (-1810.5228, 801.1111) -> (-1810.5228, 819.5556)
  line L81 (-1882.5228, 801.1111) -> (-1810.5228, 801.1111)
  line L82 (-1882.5228, 782.6667) -> (-1882.5228, 764.2222)
  line L83 (-1810.5228, 782.6667) -> (-1882.5228, 782.6667)
  line L84 (-1810.5228, 764.2222) -> (-1810.5228, 782.6667)
  line L85 (-1882.5228, 764.2222) -> (-1810.5228, 764.2222)
  line L86 (-1501.3006, 612.3334) -> (-1501.3006, 684.3334)
  line L87 (-1519.745, 612.3334) -> (-1501.3006, 612.3334)
  line L88 (-1519.745, 684.3334) -> (-1519.745, 612.3334)
  line L89 (-1501.3006, 684.3334) -> (-1519.745, 684.3334)
  line L90 (-1648.8562, 612.3334) -> (-1648.8562, 684.3334)
  line L91 (-1667.3006, 612.3334) -> (-1648.8562, 612.3334)
  line L92 (-1667.3006, 684.3334) -> (-1667.3006, 612.3334)
  line L93 (-1648.8562, 684.3334) -> (-1667.3006, 684.3334)
  line L94 (-1538.1895, 612.3334) -> (-1538.1895, 684.3334)
  line L95 (-1556.6339, 612.3334) -> (-1538.1895, 612.3334)
  line L96 (-1556.6339, 684.3334) -> (-1556.6339, 612.3334)
  line L97 (-1538.1895, 684.3334) -> (-1556.6339, 684.3334)
  line L98 (-1575.0784, 612.3334) -> (-1575.0784, 684.3334)
  line L99 (-1593.5228, 612.3334) -> (-1575.0784, 612.3334)
  line L100 (-1593.5228, 684.3334) -> (-1593.5228, 612.3334)
  line L101 (-1575.0784, 684.3334) -> (-1593.5228, 684.3334)
  line L102 (-1611.9673, 612.3334) -> (-1611.9673, 684.3334)
  line L103 (-1630.4117, 612.3334) -> (-1611.9673, 612.3334)
  line L104 (-1630.4117, 684.3334) -> (-1630.4117, 612.3334)
  line L105 (-1611.9673, 684.3334) -> (-1630.4117, 684.3334)
  line L106 (-1722.6339, 612.3334) -> (-1722.6339, 684.3334)
  line L107 (-1741.0784, 612.3334) -> (-1722.6339, 612.3334)
  line L108 (-1741.0784, 684.3334) -> (-1741.0784, 612.3334)
  line L109 (-1722.6339, 684.3334) -> (-1741.0784, 684.3334)
  line L110 (-1685.745, 612.3334) -> (-1685.745, 684.3334)
  line L111 (-1704.1895, 612.3334) -> (-1685.745, 612.3334)
  line L112 (-1704.1895, 684.3334) -> (-1704.1895, 612.3334)
  line L113 (-1685.745, 684.3334) -> (-1704.1895, 684.3334)
  line L114 (-1771.5228, 659.7334) -> (-1768.5228, 662.7334)
  line L115 (-1771.5228, 636.9334) -> (-1771.5228, 659.7334)
  line L116 (-1768.5228, 633.9334) -> (-1771.5228, 636.9334)
  line L117 (-1763.8014, 633.9334) -> (-1768.5228, 633.9334)
  line L118 (-1759.5228, 603.3334) -> (-1759.5228, 629.6548)
  line L119 (-1671.5792, 603.3334) -> (-1759.5228, 603.3334)
  line L120 (-1667.3006, 594.3334) -> (-1667.3006, 599.0548)
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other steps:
base_feature "Base Feature1" bodies "rail1"
base_feature "Base Feature1" bodies "back"
base_feature "Base Feature1" bodies "lvl0"
base_feature "Base Feature1" bodies "lvl2"
base_feature "Base Feature1" bodies "lvl1"
base_feature "Base Feature1" bodies "roof"
base_feature "Base Feature1" bodies "wall0"
base_feature "Base Feature1" bodies "leftwall"
base_feature "Base Feature1" bodies "wall1"
base_feature "Base Feature1" bodies "rightwall"
base_feature "Base Feature1" bodies "wall2"
base_feature "Base Feature1" bodies "kerf"
base_feature "Base Feature1"
create_component "CreateComponent13"
remove_body "RemoveBody12"
create_component "CreateComponent14"
remove_body "RemoveBody13"
create_component "CreateComponent15"
remove_body "RemoveBody14"
create_component "CreateComponent16"
remove_body "RemoveBody15"
create_component "CreateComponent17"
remove_body "RemoveBody16"
create_component "CreateComponent18"
remove_body "RemoveBody17"
create_component "CreateComponent19"
remove_body "RemoveBody18"
create_component "CreateComponent20"
remove_body "RemoveBody19"
create_component "CreateComponent21"
remove_body "RemoveBody20"
create_component "CreateComponent22"
remove_body "RemoveBody21"
create_component "CreateComponent23"
remove_body "RemoveBody22"
create_component "CreateComponent24"
remove_body "RemoveBody23"
create_component "CreateComponent28"
create_component "CreateComponent1"
remove_body "RemoveBody24"
remove_body "RemoveBody25"
remove_body "RemoveBody26"
remove_body "RemoveBody27"
remove_body "RemoveBody28"
remove_body "RemoveBody29"
remove_body "RemoveBody30"
remove_body "RemoveBody31"
remove_body "RemoveBody32"
remove_body "RemoveBody33"
named bodies: "wall2", "rightwall", "wall1", "leftwall", "wall0", "roof", "lvl1", "lvl2", "lvl0", "back", "rail1", "kerf", "Dogbones", "Dogbones (1)", "Dogbones1", "Dogbones2", "Dogbones (2)", "Dogbones (3)", "Dogbones (4)", "Dogbones (5)", "Dogbones (6)", "Dogbones (7)"

design "Component3"
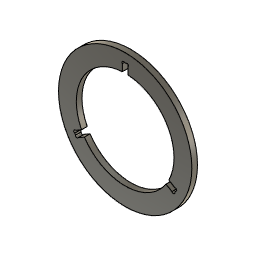
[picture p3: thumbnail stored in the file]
base_feature "Base Feature2"
base_feature "Base Feature1"
combine "Combine2"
